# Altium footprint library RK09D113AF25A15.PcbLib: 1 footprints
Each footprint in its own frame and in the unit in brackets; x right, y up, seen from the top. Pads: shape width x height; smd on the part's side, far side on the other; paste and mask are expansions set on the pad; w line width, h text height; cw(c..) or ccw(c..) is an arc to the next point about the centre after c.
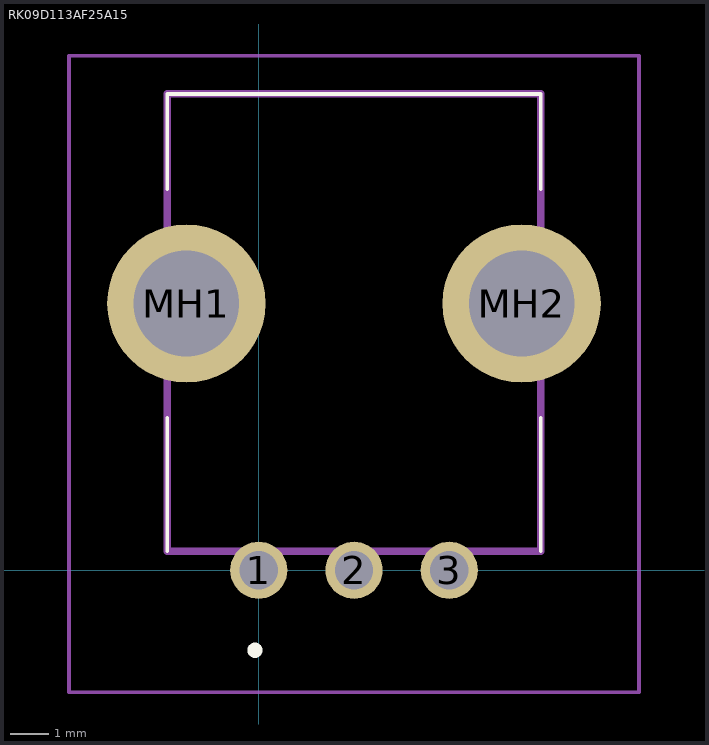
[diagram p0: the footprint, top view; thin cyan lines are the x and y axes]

## RK09D113AF25A15 [mm]
pads (5):
  round 1.5 hole 1: 1(0,0) 2(2.5,0) 3(5,0)
  round 4.155 hole 2.77: MH1(-1.9,7) MH2(6.9,7)
Top Overlay:
  lines w0.1: -2.4,0.5 -2.4,4 ; -2.4,10 -2.4,12.5 7.4,12.5 7.4,10 ; 7.4,0.5 7.4,4
  lines w0.2: -0.1,-2.2 cw(c-0.1,-2.1) -0.1,-2 ; -0.1,-2.2 -0.1,-2.2 ; -0.1,-2.2 ccw(c-0.1,-2.1) -0.1,-2 ; -0.1,-2 -0.1,-2
Mechanical 15:
  lines w0.2: -2.4,0.5 7.4,0.5 7.4,12.5 -2.4,12.5 -2.4,0.5
Mechanical 20:
  lines w0.1: -4.978,-3.2 9.978,-3.2 9.978,13.5 -4.978,13.5 -4.978,-3.2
